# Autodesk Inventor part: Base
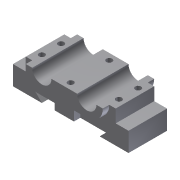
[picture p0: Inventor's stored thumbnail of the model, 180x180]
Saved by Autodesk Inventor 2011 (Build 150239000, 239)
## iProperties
Shininess: 77.0
Length Units: 11269
Angle Units: 11279
Time Units: 11290
Mass Units: 11283
Length Display Precision: 3
Angle Display Precision: 2
Created: 2002-02
Part Number: Base
Document SubType Name: Modeling
Designer: ***
Density: 1 g/cm^3
Density: 0.0
Volumn: 0.0
Area: 0.0
PropertySet Name: Model Information
Control State: 0
Master: False
Checked Out: False
Author: ***
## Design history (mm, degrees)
sketch "Sketch2"
  geometry: L1 (-10.066, -1.263)-(24.934, -1.263); L2 (37.434, 11.237)-(32.434, 11.237); L3 (17.434, 11.237)-(-2.566, 11.237); L4 (-17.566, 11.237)-(-22.566, 11.237); A1 r 12.5 centre (-10.066, 11.237) between (-22.566, 11.237) and (-10.066, -1.263); A2 r 12.5 centre (24.934, 11.237) between (24.934, -1.263) and (37.434, 11.237); A3 r 7.5 centre (24.934, 11.237) between (17.434, 11.237) and (32.434, 11.237); A4 r 7.5 centre (-10.066, 11.237) between (-17.566, 11.237) and (-2.566, 11.237)
  constraints: 8 end point, 8 point on circle, 4 centre point, 3 horizontal, 3 parallel, 2 coincident, 2 equal radius, 2 tangent
  dimensions: "d0" = 12.5 radius of A1; "d1" = 7.5 radius of A4; "d2" = 35 distance of A1.centre A2.centre; "d3" = 12.5 distance between parallel lines of L3 L1
extrude "Extrusion1" new body sketch "Sketch2" stored distance "d4" = 40; taper "d5" = 0 deg
sketch "Sketch4"
  geometry: L1 (-27.566, 1.237)-(-37.566, 1.237); L2 (-37.566, 1.237)-(-37.566, -13.763); L3 (-37.566, -13.763)-(-15.066, -13.763); L4 (-15.066, -13.763)-(-20.066, -8.763); L5 (-20.066, -8.763)-(34.934, -8.763); L6 (34.934, -8.763)-(29.934, -13.763); L7 (29.934, -13.763)-(52.434, -13.763); L8 (52.434, -13.763)-(52.434, 1.237); L9 (52.434, 1.237)-(42.434, 1.237); L10 (24.934, -1.263)-(-10.066, -1.263); L11 (-17.566, 11.237)-(-22.566, 11.237) reference; L12 (37.434, 11.237)-(32.434, 11.237) reference; L13 (-22.566, 11.237)-(-27.566, 11.237); L14 (-27.566, 11.237)-(-27.566, 1.237); L15 (37.434, 11.237)-(42.434, 11.237); L16 (42.434, 11.237)-(42.434, 1.237); A1 r 12.5 centre (24.934, 11.237) between (24.934, -1.263) and (37.434, 11.237); A2 r 12.5 centre (-10.066, 11.237) between (-22.566, 11.237) and (-10.066, -1.263); A3 r 12.5 centre (24.934, 11.237) between (24.934, -1.263) and (37.434, 11.237) reference; A4 r 12.5 centre (-10.066, 11.237) between (-22.566, 11.237) and (-10.066, -1.263) reference
  constraints: 28 end point, 6 perpendicular, 5 equal length, 4 concentric, 4 parallel, 4 point on circle, 2 centre point, 2 collinear, 1 tangent
  dimensions: "d12" = 15 distance of L1.end L2.end; "d13" = 25 distance from line of L3 L11.end; "d14" = 90 distance between parallel lines of L2 L8; "d15" = 5 distance between parallel lines of L5 L7; "d16" = 22.5 distance of L2.end L3.end; "d24" = 5 distance of L12.start L15.end; "d25" = 15 distance from line of L8 L12.start
extrude "Extrusion3" join sketch "Sketch4" stored distance "d17" = 30; taper "d18" = 0 deg
sketch "Sketch5"
  geometry: L1 (-14.934, -1.263)-(0.066, -1.263); L2 (0.066, -1.263)-(0.066, -8.763); L3 (0.066, -8.763)-(-14.934, -8.763); L4 (-14.934, -8.763)-(-14.934, -1.263); L5 (10.066, -1.263)-(-24.934, -1.263) reference; 1 further point
  constraints: 8 end point, 2 parallel, 1 collinear, 1 horizontal, 1 perpendicular
  dimensions: "d19" = 7.5 distance of L1.end L2.end; "d20" = 15 distance of L2.end L3.end; "d21" = 15 distance from line of point (-29.934, -13.763) L4
extrude "Extrusion4" join sketch "Sketch5" distance "d22" = 40; taper "d23" = 0 deg
sketch "Sketch6"
  geometry: L1 (-5, -35)-(0, -35) reference; L2 (-5, -35)-(-5, -5) reference; 1 further point
  dimensions: "d26" = 7.5 distance from line of L1 point (0, -27.5); "d27" = 5 distance from line of L2 point (0, -27.5)
hole "Hole1" sketch "Sketch6" at (0, -27.5) diameter "d28" = 4.5; stored, may be unused: countersink angle "d32" = 82 deg, drill point angle "d34" = 0 deg; dims "d29" = 6, "d30" = 4, "d31" = 2, "d33" = 15
pattern_linear "Rectangular Pattern1" dims "d37" = 60, "d40" = 15
sketch "Sketch7"
  geometry: L1 (-20, -40)-(-20, -35) reference; L2 (0, -40)-(20, -40) reference; 1 further point
  dimensions: "d41" = 30 distance from line of L1 point (10, -35); "d42" = 5 distance from line of L2 point (10, -35)
hole "Hole2" sketch "Sketch7" at (10, -35) diameter "d43" = 4.5; stored, may be unused: countersink angle "d47" = 82 deg, drill point angle "d49" = 0 deg; dims "d44" = 6, "d45" = 4, "d46" = 2, "d48" = 15
pattern_linear "Rectangular Pattern2" dims "d52" = 30
body "Solid1"
